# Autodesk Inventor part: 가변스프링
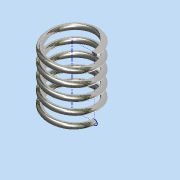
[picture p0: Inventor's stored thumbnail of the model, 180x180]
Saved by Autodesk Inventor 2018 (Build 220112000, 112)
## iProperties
Created: 2022-09
Part Number: 가변스프링
Material: 스테인레스 스틸
Document SubType Name: Modeling
Designer: home
Density: 8 g/cm^3
Appearance: 반연마
Mass: 6.5852 g
Surface Area: 16.7317 cm^2
Volume: 0.82315 cm^3
Author: home
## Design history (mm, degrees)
sketch "스케치2"
  geometry: L1 (0, 0)-(-8.5, 0); L2 (-8.5, 0)-(-8.5, 22.5); L3 (-8.5, 22.5)-(0, 22.5); L4 (0, 22.5)-(0, 0); C1 r 1 at (-8.5, 0)
  constraints: 8 end point, 2 parallel, 1 centre point, 1 coincident, 1 horizontal, 1 perpendicular
  dimensions: "d0" = 17 diameter of L2 L4; "d1" = 22.5 distance of L1.end L2.end (derived); "d2" = 2 diameter of C1
feature "코일1" sketch "스케치2" pitch "d3" = 10; turns "d5" = 5; dims "d4" = 22.5 (= d1), "d6" = 0, angle "d7" = 90 deg, angle "d8" = 90 deg, "d9" = 0, "d10" = 0
node "작업 평면1"
sketch "스케치3"
  geometry: L1 (1, 0)-(-1, 0) reference; 1 further point
  constraints: 1 horizontal alignment
extrude "돌출1" cut sketch "스케치3" extent not by distance; stored distance "d11" = 10; taper "d12" = 0 deg
sketch "스케치4"
  geometry: L1 (7.5, 0)-(9.5, 0) reference; 1 further point
  constraints: 1 horizontal alignment
extrude "돌출2" cut sketch "스케치4" extent not by distance; stored distance "d13" = 10; taper "d14" = 0 deg
node "솔리드1"
node "절단 모서리 투영1"
node "절단 모서리 투영2"
